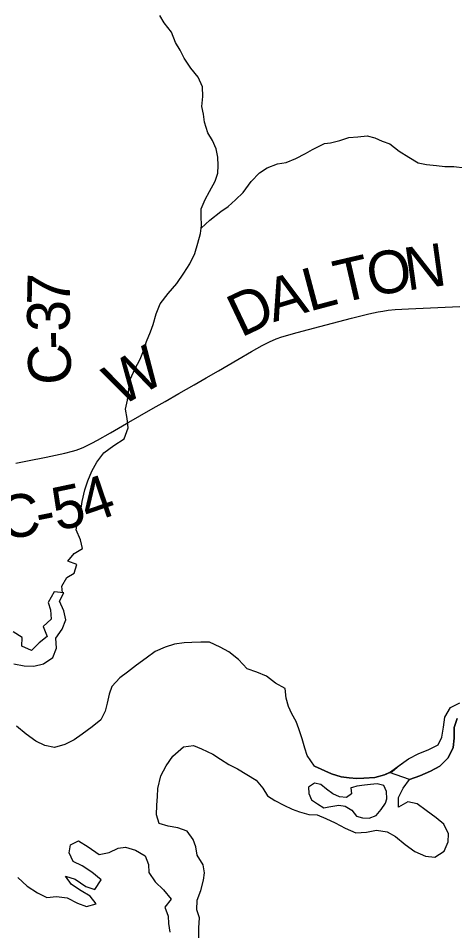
# Model space of a CAD drawing. Extents: x 1442749 to 1756758, y 235267 to 677782.
# Drawn here: x 1577781 to 1580840, y 504843 to 511240 of the extents above; entities that cross this region are included whole.
import ezdxf

# ---------------------------------------------------------------- set-up
doc = ezdxf.new("R2010")
doc.units = 0
for name, color, linetype in [('GM_X_County_Road', 7, 'Continuous'), ('GM_X_County_Road_Text', 7, 'Continuous'), ('GM_X_Major_Lake', 7, 'Continuous'), ('GM_X_Major_River', 7, 'Continuous'), ('GM_X_Minor_River', 7, 'Continuous')]:
    doc.layers.add(name, color=color, linetype=linetype)

msp = doc.modelspace()

# ---------------------------------------------------------------- linework, layer by layer
at = {"layer": 'GM_X_County_Road'}
msp.add_lwpolyline([(1577764, 508121.5), (1577846, 508137.7), (1577977.8, 508163.5), (1578108.9, 508190.8), (1578162.6, 508204.2), (1578187.9, 508212.3), (1578205.7, 508218.3), (1578225.2, 508225.8), (1578241.7, 508233.3), (1578297, 508260.9), (1578337.4, 508282.4), (1578428.3, 508334.6), (1578539.1, 508398.7), (1578726.8, 508506.8), (1578809.8, 508553), (1578906.4, 508608.4), (1579014.3, 508669.6), (1579099.2, 508718.7), (1579184, 508767.9), (1579319.4, 508847.8), (1579415.6, 508904.3), (1579490.2, 508946.1), (1579543.3, 508972.5), (1579589, 508991.7), (1579629.5, 509005.6), (1579736.6, 509037.6), (1579895, 509080.1), (1580117.1, 509138.1), (1580238.2, 509168), (1580302.6, 509181.1), (1580337.6, 509187.4), (1580374.1, 509192.8), (1580423.3, 509197.5), (1580515.2, 509202.5), (1580774.2, 509213.8), (1580875.5, 509219.2)], dxfattribs=at)
at = {"layer": 'GM_X_Major_Lake'}
msp.add_line((1580524.1, 505903.5), (1580382.9, 505951.7), dxfattribs=at)
for points in [[(1577749.5, 506713.2), (1577823.1, 506701.1), (1577891, 506697.3), (1577957.5, 506713.5), (1578022.8, 506759.7), (1578048.7, 506825.1), (1578044.7, 506893.3), (1578088.5, 506956.2), (1578114.4, 507023.6), (1578100.2, 507086.1), (1578070.1, 507153), (1578099.8, 507212.3), (1578034, 507218.1), (1577991.8, 507143.2), (1578006.4, 507092.7), (1578012.5, 507028.4), (1577955, 506975.9), (1577985.1, 506907), (1577927.7, 506860.5), (1577874.2, 506807.9), (1577807.1, 506837.8), (1577808.8, 506899.9), (1577745.9, 506937.7)], [(1579857.1, 505997.8), (1579807.2, 506071.3), (1579788.7, 506123.9), (1579770.6, 506188.5), (1579748.6, 506259.2), (1579728, 506309.8), (1579699.6, 506364.7), (1579675.1, 506415.5), (1579658.7, 506474), (1579652.7, 506542.3), (1579583.7, 506578.2), (1579521.1, 506628), (1579453.9, 506656), (1579384.6, 506679.9), (1579324.5, 506743.7), (1579258, 506797.6), (1579197, 506831.3), (1579121.9, 506865.5), (1579062, 506867.1), (1578997.9, 506864.9), (1578943.8, 506862.4), (1578875.5, 506852.3), (1578811, 506832), (1578740, 506799.9), (1578678.7, 506753.6), (1578609.3, 506705.4), (1578547.9, 506657), (1578492.8, 506616.5), (1578437, 506555.9), (1578419.5, 506502.3), (1578403.7, 506438.7), (1578390.1, 506383), (1578360.3, 506321.7), (1578298.9, 506273.3), (1578229.4, 506221.2), (1578172.3, 506180.7), (1578107.3, 506148.4), (1578034.7, 506128.4), (1577967.1, 506142.3), (1577904, 506172.1), (1577837.4, 506222), (1577769, 506278)], [(1579046.4, 504788.4), (1579046.6, 504864.5), (1579050.5, 504932.5), (1579032.2, 504989.1), (1579034.1, 505057.1), (1579062, 505124.5), (1579080.1, 505198), (1579087.6, 505249.9), (1579077.2, 505304.3), (1579035.2, 505373.6), (1579024.8, 505432), (1579008.3, 505482.5), (1578966, 505541.8), (1578898.7, 505565.6), (1578832.9, 505575.5), (1578769.5, 505595.3), (1578749.2, 505655.9), (1578753.2, 505723.9), (1578756.9, 505783.9), (1578760.5, 505839.9), (1578781.1, 505929.5), (1578817.1, 505998.6), (1578865, 506067.3), (1578938.9, 506131.4), (1579009.2, 506141.5), (1579066.5, 506117.8), (1579145.5, 506081.6), (1579198.5, 506046.1), (1579257.4, 506008.4), (1579318.5, 505978.7), (1579383.4, 505938.8), (1579448.2, 505899), (1579494.6, 505841.6), (1579529.1, 505788.5), (1579580.1, 505755.1), (1579643.2, 505723.3), (1579700.4, 505695.7), (1579751.9, 505676.2), (1579817.4, 505658.4), (1579877.3, 505656.7)], [(1580382.9, 505951.7), (1580348.4, 505935.3), (1580279.8, 505916.7), (1580203.6, 505912.3), (1580153.4, 505909.3), (1580099.4, 505914.5), (1580045.4, 505921.6), (1579977.8, 505943.1), (1579857.1, 505997.8)], [(1579857.1, 505997.8), (1579977.8, 505943.1), (1580045.4, 505921.6), (1580099.4, 505914.5), (1580153.4, 505909.3), (1580203.6, 505912.3), (1580279.8, 505916.7), (1580348.4, 505935.3), (1580401.1, 505960.3)], [(1579877.3, 505656.7), (1579937.1, 505629), (1580002.3, 505599.4), (1580073.6, 505561.8), (1580147.1, 505530.1), (1580221.3, 505534.5), (1580291.8, 505547.1), (1580365.7, 505537.5), (1580425.1, 505504.2), (1580494, 505448.5), (1580561.1, 505398.9), (1580634.5, 505365.3), (1580700.5, 505359.8), (1580765.6, 505400.6), (1580795.1, 505466.2), (1580796.3, 505522.4), (1580763.7, 505589.3), (1580710.6, 505634.6), (1580639.5, 505686.3), (1580576.4, 505731.8), (1580510.6, 505747.2), (1580445.6, 505708.5), (1580447.1, 505776.7), (1580478.6, 505842.2), (1580524.1, 505903.5)], [(1579877.3, 505656.7), (1579937.1, 505629), (1580002.3, 505599.4), (1580073.6, 505561.8), (1580147.1, 505530.1), (1580221.3, 505534.5), (1580291.8, 505547.1), (1580365.7, 505537.5), (1580425.1, 505504.2), (1580494, 505448.5), (1580561.1, 505398.9), (1580634.5, 505365.3), (1580700.5, 505359.8), (1580765.6, 505400.6), (1580795.1, 505466.2), (1580796.3, 505522.4), (1580763.7, 505589.3), (1580710.6, 505634.6), (1580639.5, 505686.3), (1580576.4, 505731.8), (1580510.6, 505747.2), (1580445.6, 505708.5), (1580447.1, 505776.7), (1580478.6, 505842.2), (1580524, 505903.5)], [(1580124.8, 505847.7), (1580113.1, 505843.9), (1580116.6, 505803.8), (1580082.2, 505778.1), (1580032.2, 505782.7), (1579986.3, 505803.3), (1579942.6, 505835.8), (1579900.9, 505868.4), (1579856.9, 505877), (1579816.5, 505849.3), (1579818, 505805.2), (1579837.5, 505760.8), (1579879.2, 505732.3), (1579923, 505703.7), (1579957.7, 505710.8)], [(1579957.7, 505710.8), (1580027.4, 505722.5), (1580071.4, 505716), (1580119.2, 505689.4), (1580150.8, 505646.9), (1580194.7, 505634.4), (1580240.8, 505631.9), (1580289.1, 505651.4), (1580325.7, 505693.1), (1580354.3, 505736.8), (1580364.7, 505768.8), (1580361.3, 505819), (1580343.8, 505861.3), (1580297.8, 505871.9), (1580249.6, 505868.4), (1580207.5, 505862.9), (1580155.3, 505857.5), (1580124.8, 505847.7)], [(1577778.6, 505216.1), (1577842.9, 505156.2), (1577915.5, 505108.1), (1577980.6, 505076.3), (1578048.8, 505082.4), (1578124.5, 505074.3), (1578197.5, 505036.2), (1578258.8, 505012.5), (1578327.4, 505032.6), (1578284.9, 505085.9), (1578222, 505123.7), (1578155.2, 505167.6), (1578112.9, 505224.9), (1578180.3, 505205), (1578254.8, 505152.8), (1578318.2, 505133), (1578362.2, 505199.9), (1578297.7, 505253.8), (1578229, 505297.8), (1578165.9, 505329.6), (1578137.6, 505390.4), (1578147.1, 505444.3), (1578204, 505472.7)], [(1578204, 505472.7), (1578270.8, 505430.8), (1578349.3, 505378.6), (1578417.6, 505390.7), (1578480.5, 505421), (1578532.8, 505429.6), (1578602.1, 505407.6), (1578671, 505367.6), (1578693.2, 505306.9), (1578697.6, 505250.7), (1578739.8, 505185.5), (1578800.2, 505129.7), (1578852.3, 505064.2), (1578808.7, 505009.3), (1578830.9, 504944.6), (1578833.4, 504894.4), (1578843.6, 504832)]]:
    msp.add_lwpolyline(points, dxfattribs=at)
at = {"layer": 'GM_X_Major_River'}
msp.add_line((1580524.1, 505903.5), (1580382.9, 505951.7), dxfattribs=at)
for points in [[(1580382.9, 505951.7), (1580517.2, 506048.2), (1580588.1, 506084.8), (1580654.9, 506111.5), (1580723.8, 506146.2), (1580751, 506199.8), (1580760.6, 506269.9), (1580772.1, 506339.9), (1580809.7, 506407.3), (1580876.6, 506442)], [(1580401.1, 505960.3), (1580452, 506001.4), (1580517.2, 506048.2), (1580588.1, 506084.8), (1580654.9, 506111.5), (1580723.8, 506146.2), (1580751, 506199.8), (1580760.6, 506269.9), (1580772.1, 506339.9), (1580809.7, 506407.3), (1580876.6, 506442)], [(1580524, 505903.5), (1580594.7, 505928.1), (1580669.6, 505960.7), (1580736.5, 505997.4), (1580794, 506056.4), (1580829.6, 506127.9), (1580837, 506192), (1580836.7, 506268.3), (1580858.1, 506330)], [(1580858.1, 506330), (1580836.7, 506268.3), (1580837, 506192), (1580829.6, 506127.9), (1580794, 506056.4), (1580736.5, 505997.4), (1580669.6, 505960.7), (1580594.7, 505928.1), (1580524.1, 505903.5)]]:
    msp.add_lwpolyline(points, dxfattribs=at)
at = {"layer": 'GM_X_Minor_River'}
for points in [[(1578092.5, 507212.9), (1578087.5, 507258.3), (1578120.8, 507319.7), (1578173.4, 507350.8), (1578192.6, 507410.5), (1578129.1, 507433.8), (1578172.2, 507487), (1578230.9, 507521.9), (1578218.2, 507584.2), (1578187.6, 507653), (1578198.9, 507716.8), (1578220.4, 507788.5), (1578229.7, 507852.4), (1578247.4, 507934.2), (1578268.7, 507997.9), (1578298.1, 508065.4), (1578331.4, 508128.9), (1578380.8, 508194), (1578451.8, 508244.7), (1578522.8, 508291.4), (1578552.4, 508368.9), (1578545.7, 508433.1), (1578533.1, 508499.5), (1578546.4, 508563.3), (1578555.9, 508639.3), (1578567.4, 508713.2), (1578598.8, 508780.6), (1578636.3, 508850), (1578663.7, 508919.6), (1578680.8, 508973.3), (1578708.2, 509040.9), (1578727.3, 509092.6), (1578748.8, 509168.3), (1578776.2, 509237.9), (1578831.8, 509310.9), (1578893.2, 509379.8), (1578940.7, 509453), (1578984, 509518.2), (1579019.5, 509591.6), (1579041, 509663.3), (1579058.4, 509731.1), (1579065.6, 509787), (1579062.9, 509853.2), (1579063.9, 509903.2), (1579091.3, 509968.8), (1579120.5, 510026.3), (1579162, 510097.6), (1579181.1, 510155.3), (1579182.2, 510207.4), (1579179.4, 510267.5), (1579168.6, 510325.9), (1579141.8, 510382.5), (1579110.9, 510437.2), (1579086.4, 510511.8), (1579079.6, 510568), (1579068.7, 510622.3), (1579074.2, 510692.3), (1579073.5, 510760.4), (1579042.9, 510827.1), (1578990.2, 510890.3), (1578943.6, 510959.3), (1578916.8, 511015.9), (1578883.9, 511070.7), (1578855.4, 511143.4), (1578804.7, 511208.5), (1578773.7, 511259.2)], [(1579928.7, 510363), (1579968.6, 510366.4), (1580034.9, 510383.7), (1580097.3, 510403.1), (1580161.5, 510408.3), (1580227.7, 510415.6), (1580279.7, 510403), (1580331.5, 510378.3), (1580385.4, 510359.6), (1580450.9, 510308.7), (1580518.5, 510265.8), (1580584.2, 510227), (1580642.2, 510214.3), (1580712.3, 510207.5), (1580770.3, 510200.8), (1580834.4, 510202), (1580910.5, 510191.1)], [(1579063.3, 509769.7), (1579124.3, 509823.9), (1579201.6, 509884.5), (1579252.3, 509919.5), (1579303.3, 509966.6), (1579358.4, 510019.6), (1579413.9, 510094.6), (1579473.2, 510155.6), (1579525.9, 510190.6), (1579598.5, 510219.2), (1579658.7, 510230), (1579727.3, 510256.7), (1579794, 510291.4), (1579844.6, 510320.5), (1579928.7, 510363)]]:
    msp.add_lwpolyline(points, dxfattribs=at)

# ---------------------------------------------------------------- texts
at = {"layer": 'GM_X_County_Road_Text'}
for s, rotation, p in [('O', 9.02395, (1580247.8, 509289.7)), ('N', 7.87148, (1580506.9, 509330.9)), ('T', 13.0685, (1580034.7, 509240.1)), ('L', 14.89691, (1579820.3, 509183)), ('7', 88.72748, (1578142.5, 509225.2)), ('A', 16.6019, (1579569.6, 509108.2)), ('D', 25.41479, (1579342.5, 508999.3)), ('3', 90.32526, (1578143.6, 509042.7)), ('-', 91.4559, (1578146.7, 508921.1)), ('C', 92.09251, (1578155.6, 508675.7)), ('W', 29.74522, (1578496.8, 508512.6)), ('4', 18.78926, (1578271.2, 507695.2)), ('5', 11.93017, (1578052.6, 507646.6)), ('C', 7.5152, (1577662.8, 507585.4)), ('-', 11.531, (1577929.7, 507621.5))]:
    msp.add_text(s, height=300, rotation=rotation, dxfattribs=at).set_placement(p)

doc.saveas('drawing.dxf')
